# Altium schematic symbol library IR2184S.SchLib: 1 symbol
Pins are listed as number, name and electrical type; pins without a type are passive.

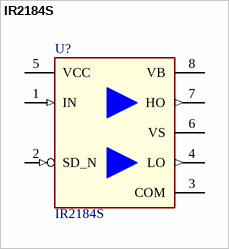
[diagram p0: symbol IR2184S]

## IR2184S
designator U?
Half-Bridge Driver; Manufacturer: Infineon Technologies
pins: 1 IN (in) "Logic input for high-side and low-side gate driver outputs (HO and LO)", 2 SD_N (in) "Logic Input for Shutdown", 3 COM "Low Side Return", 4 LO (out) "Low side gate drive output", 5 VCC (power) "Low-side and logic fixed supply", 6 VS (power) "High-side floating supply return", 7 HO (out) "High-side gate drive output", 8 VB (power) "High-side floating supply"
